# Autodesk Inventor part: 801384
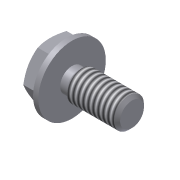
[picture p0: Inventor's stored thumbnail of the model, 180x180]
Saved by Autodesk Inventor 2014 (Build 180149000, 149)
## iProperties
IsCustomPart: 0
Created: 2007-03
Part Number: 801384
Material: Steel, High Strength Low Alloy
Description: AS 1427 - M3 X 6
Document SubType Name: Modeling
Standard: AS 1427
Designer: JJ
Standards Organization: AS
Language: en-US
Size Designation: M3 x 6
Categories: <MemberInstance><Categories><Category DisplayName="Fasteners" InternalName="e4da775c-781d-43d5-af7c-5136215cf5a6" Mnemonic="FSTN"><Category DisplayName="Bolts"
Density: 7.84 g/cm^3
Mass: 0.76575 g
Surface Area: 1.6834 cm^2
Volume: 0.0976721 cm^3
Appearance: Steel - Polished
Component Category: Fasteners
Author: JJ
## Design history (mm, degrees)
sketch "Sketch1"
  geometry: L1 (0, 3.375)-(0, 1.193); L2 (1, 1.5)-(6, 1.5); L3 (6, 1.5)-(6, 0); L4 (6, 0)-(-0.53, 0); L5 (0, -0.675)-(0, 4.05) reference; L6 (-1.836, 0)-(7.306, 0) reference; L7 (-0.53, 0)-(-0.53, 3.375); L8 (-0.53, 3.375)-(0, 3.375); L9 (1, 1.5)-(0.693, 1.193); L10 (0.693, 1.193)-(0, 1.193)
  constraints: 16 end point, 2 perpendicular, 2 point on line, 1 collinear, 1 parallel
  dimensions: "d0" = 6 distance between parallel lines of L3 L1 (= NLG); "d1" = 5 distance from line of L2.start L3 (= GEL); "d2" = 3 diameter of L2 L4 (= GD); "d8" = 0.53 distance between parallel lines of L7 L1 (= PHH); "d9" = 6.75 diameter of L8 L4 (= LADI); "d15" = 2.38655 diameter of L10 L4 (= BDM); "d16" = 0.30673 horizontal distance of L2.start L9.end (= GAL)
revolve "Body" sketch "Sketch1" stored, may be unused: angle "d12" = 90 deg
sketch "Sketch2"
  geometry: L1 (0, 2.887)-(2.5, 1.443); L2 (2.5, 1.443)-(2.5, -1.443); L3 (2.5, -1.443)-(0, -2.887); L4 (0, -2.887)-(-2.5, -1.443); L5 (-2.5, -1.443)-(-2.5, 1.443); L6 (-2.5, 1.443)-(0, 2.887); C1 r 3.375 at (0, 0) reference; C2 r 3.375 at (0, 0) reference; 1 further point
  constraints: 12 end point, 1 coincident, 1 vertical, 11 other
  dimensions: "d10" = 5 distance between parallel lines of L5 L2 (= SW)
extrude "Head" join sketch "Sketch2" distance "d3" = 2.36 (= KOH); taper "d4" = 0 deg
revolve "Chamfer1" stored, may be unused: angle "d21" = 90 deg
workplane "Work Plane1"
body "Solid1"
feature "Thread" dims "d13" = 5 (= GEL), "d14" = 0
chamfer "Chamfer2" distance "d6" = 0.30673 (= -0.5 x SPD + 0.5 x GD); stored, may be unused: second distance "d7" = 0.30683 (computed from GUL), angle "d41" = 45 deg
sketch "Sketch3"
  geometry: L1 (-2.36, 2.25)-(-2.36, 2.887); L2 (-2.36, 2.887)-(-1.992, 2.887); L3 (-1.992, 2.887)-(-2.36, 2.25); L4 (-1.765, 2.887)-(-2.36, 2.887); L5 (-2.36, 2.887)-(-2.36, 0.577); L6 (-0.53, 2.887)-(-2.36, 2.887) reference; L7 (-2.36, 2.887)-(-2.36, 1.443) reference; L8 (-2.726, 0)-(-0.164, 0) reference
  constraints: 10 end point, 4 collinear, 1 perpendicular, 1 vertical
  dimensions: "d5" = 30 deg angle of L3 L1 (= ANG1); "d18" = 4.5 diameter of L1.start L8 (= SW0)
other parameters: "NLG" = 6 [user parameter; used in 1 equation term], "GD" = 3 (= NND) [user parameter; used in 2 equation terms], "BDM" = 2.38655 (= NND - 1.2269 x PTC) [user parameter; used in 1 equation term], "KOH" = 2.36 [user parameter; used in 1 equation term], "GEL" = 5 [user parameter; used in 2 equation terms], "LADI" = 6.75 [user parameter; used in 1 equation term], "SW" = 5 [user parameter; used in 2 equation terms], "PHH" = 0.53 [user parameter; used in 2 equation terms], "SW0" = 4.5 [user parameter; used in 1 equation term], "SPD" = 2.38655 (= NND - 1.2269 x PTC) [user parameter; used in 1 equation term], "ANG1" = 30 deg [user parameter; used in 1 equation term], "GAL" = 0.30673 (= 0.61345 x PTC) [user parameter; used in 1 equation term], "GUL" = 0.30673 (= 0.61345 x PTC) [user parameter; used in 1 equation term], "d17" = 0, "d42" = 0, "d43" = 0, "WFT" = 0.53 (= PHH) [user parameter], "PTC" = 0.5 [user parameter; used in 6 equation terms], "THREADDIA" = 3 [user parameter; used in 1 equation term], "E0" = 5.775 (= 1.155 x SW) [user parameter], "TOA" = 30 deg [user parameter], "NND" = 3 [user parameter; used in 4 equation terms], "GD1" = 2.38655 (= THREADDIA - 1.2269 x PTC) [user parameter], "SDH" = 3.6 [user parameter], "KOH1" = 1.83 [user parameter], "SD2" = 3 (= NND) [user parameter], "SD" = 0 [user parameter], "RR" = 0.1 [user parameter]
